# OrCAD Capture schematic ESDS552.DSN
size A
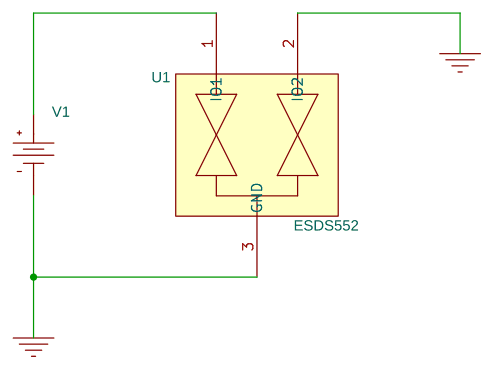
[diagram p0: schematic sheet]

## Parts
U1  ESDS552
V1  VDC

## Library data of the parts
U1 = ESDS552
V1 = VDC

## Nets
0: U1.2(IO2) U1.3(GND) V1.1(-)
N00095: U1.1(IO1) V1.0(+)
